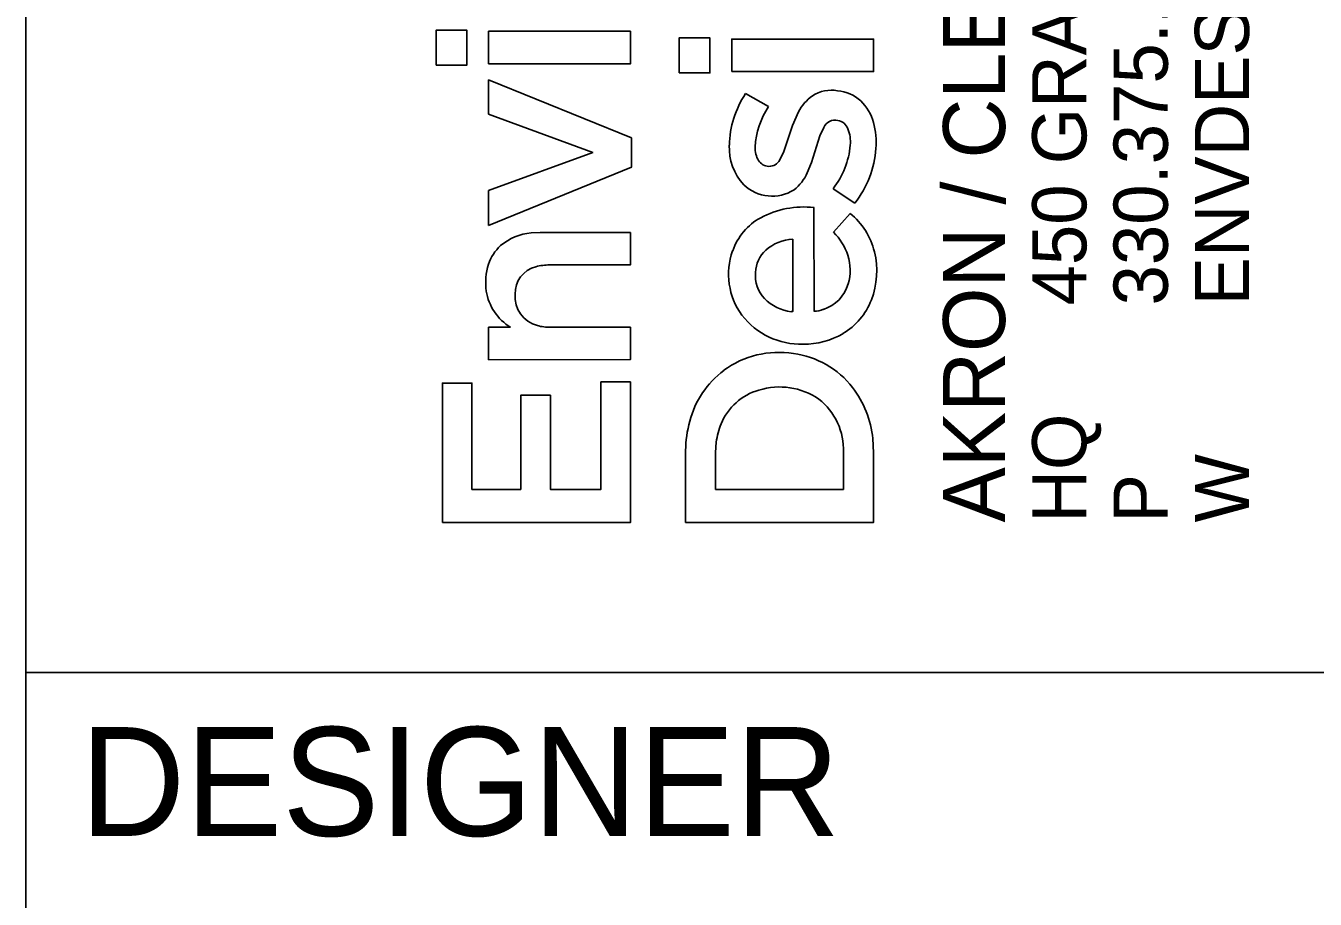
# Model space of a CAD drawing. Extents: x -0.3 to 34, y 0 to 22.
# Drawn here: x 32 to 33.185, y 2.292 to 3.094 of the extents above; entities that cross this region are included whole.
import ezdxf

# ---------------------------------------------------------------- set-up
doc = ezdxf.new("R2010")
doc.units = 0
doc.layers.add('RD_X_Misc_Items', color=7, linetype='Continuous')
doc.layers.add('SV_X_Control_Cells_Found', color=7, linetype='Continuous')

msp = doc.modelspace()

# ---------------------------------------------------------------- linework, layer by layer
at = {"layer": 'RD_X_Misc_Items'}
for p, q in [((32.3771, 3.0582), (32.3771, 3.0903)), ((32.3771, 3.0903), (32.4054, 3.0903)), ((32.4054, 3.0903), (32.4054, 3.0582)), ((32.4254, 3.0594), (32.4254, 3.0893)), ((32.4254, 3.0893), (32.5557, 3.0893)), ((32.5557, 3.0893), (32.5557, 3.0594)), ((32.6005, 3.0511), (32.6005, 3.0832)), ((32.6005, 3.0832), (32.6289, 3.0832)), ((32.6289, 3.0832), (32.6289, 3.0511)), ((32.6489, 3.0523), (32.6489, 3.0822)), ((32.6489, 3.0822), (32.7792, 3.0822)), ((32.7792, 3.0822), (32.7792, 3.0523)), ((32.4054, 3.0582), (32.3771, 3.0582)), ((32.5557, 3.0594), (32.4254, 3.0594)), ((32.6289, 3.0511), (32.6005, 3.0511)), ((32.7792, 3.0523), (32.6489, 3.0523)), ((32.4254, 3.0133), (32.4254, 3.0446)), ((32.4254, 3.0446), (32.5567, 2.9913)), ((32.6615, 3.0321), (32.6827, 3.0203)), ((32.5212, 2.978), (32.4254, 3.0133)), ((32.7048, 3.0026), (32.7104, 3.0153)), ((32.6967, 2.9787), (32.7048, 3.0026)), ((32.7334, 3.001), (32.7298, 2.9933)), ((32.5567, 2.9913), (32.5567, 2.9644)), ((32.7298, 2.9933), (32.7221, 2.9688)), ((32.4254, 2.9429), (32.5212, 2.978)), ((32.693, 2.9712), (32.6967, 2.9787)), ((32.5567, 2.9644), (32.4254, 2.9109)), ((32.7221, 2.9688), (32.7182, 2.9592)), ((32.4254, 2.9109), (32.4254, 2.9429)), ((32.7621, 2.9314), (32.742, 2.9447)), ((32.7245, 2.9275), (32.7246, 2.8319)), ((32.7423, 2.9046), (32.7577, 2.922)), ((32.4644, 2.904), (32.4729, 2.9044)), ((32.4729, 2.9044), (32.5557, 2.9044)), ((32.5557, 2.9044), (32.5557, 2.8746)), ((32.7049, 2.8318), (32.7049, 2.8983)), ((32.5557, 2.8746), (32.4814, 2.8746)), ((32.7036, 2.8317), (32.7049, 2.8318)), ((32.4254, 2.7875), (32.4254, 2.8173)), ((32.4254, 2.8173), (32.4455, 2.8173)), ((32.4822, 2.8173), (32.5557, 2.8173)), ((32.5557, 2.8173), (32.5557, 2.7876)), ((32.5557, 2.7876), (32.4254, 2.7875)), ((32.383, 2.6379), (32.383, 2.766)), ((32.383, 2.766), (32.4101, 2.766)), ((32.4101, 2.766), (32.4101, 2.6683)), ((32.5286, 2.6683), (32.5286, 2.7672)), ((32.5286, 2.7672), (32.5557, 2.7672)), ((32.5557, 2.7672), (32.5557, 2.6379)), ((32.455, 2.6683), (32.455, 2.7549)), ((32.455, 2.7549), (32.4822, 2.7549)), ((32.4822, 2.7549), (32.4822, 2.6683)), ((32.7785, 2.715), (32.7792, 2.7021)), ((32.6064, 2.638), (32.6064, 2.704)), ((32.6347, 2.7118), (32.6341, 2.7023)), ((32.6341, 2.7023), (32.6341, 2.6684)), ((32.7515, 2.6683), (32.7515, 2.7024)), ((32.7792, 2.7021), (32.7792, 2.638)), ((32.4101, 2.6683), (32.455, 2.6683)), ((32.4822, 2.6683), (32.5286, 2.6683)), ((32.6341, 2.6684), (32.7515, 2.6683)), ((32.5557, 2.6379), (32.383, 2.6379)), ((32.7792, 2.638), (32.6064, 2.638))]:
    msp.add_line(p, q, dxfattribs=at)
for points in [[(32.3771, 3.0582), (32.3771, 3.0903), (32.4054, 3.0903), (32.4054, 3.0582)], [(32.4254, 3.0594), (32.4254, 3.0893), (32.5557, 3.0893), (32.5557, 3.0594)], [(32.6005, 3.0511), (32.6005, 3.0832), (32.6289, 3.0832), (32.6289, 3.0511)], [(32.6489, 3.0523), (32.6489, 3.0822), (32.7792, 3.0822), (32.7792, 3.0523)], [(32.4254, 2.9109), (32.4254, 2.9429), (32.5212, 2.978), (32.4254, 3.0133), (32.4254, 3.0446), (32.5567, 2.9913), (32.5567, 2.9644)], [(32.383, 2.6379), (32.383, 2.766), (32.4101, 2.766), (32.4101, 2.6683), (32.455, 2.6683), (32.455, 2.7549), (32.4822, 2.7549), (32.4822, 2.6683), (32.5286, 2.6683), (32.5286, 2.7672), (32.5557, 2.7672), (32.5557, 2.6379)]]:
    msp.add_lwpolyline(points, close=True, dxfattribs=at)
for points in [[(32.6615, 3.0321), (32.6827, 3.0203)], [(32.693, 2.9712), (32.6967, 2.9787), (32.7048, 3.0026), (32.7104, 3.0153)], [(32.7334, 3.001), (32.7298, 2.9933), (32.7221, 2.9688), (32.7182, 2.9592)], [(32.7621, 2.9314), (32.742, 2.9447)], [(32.7245, 2.9275), (32.7246, 2.8319)], [(32.7423, 2.9046), (32.7577, 2.922)], [(32.4644, 2.904), (32.4729, 2.9044), (32.5557, 2.9044), (32.5557, 2.8746), (32.4814, 2.8746)], [(32.7036, 2.8317), (32.7049, 2.8318), (32.7049, 2.8983)], [(32.4254, 2.7875), (32.4254, 2.8173), (32.4455, 2.8173)], [(32.4822, 2.8173), (32.5557, 2.8173), (32.5557, 2.7876), (32.4254, 2.7875)], [(32.7785, 2.715), (32.7792, 2.7021), (32.7792, 2.638), (32.6064, 2.638)], [(32.6064, 2.638), (32.6064, 2.704)], [(32.6347, 2.7118), (32.6341, 2.7023), (32.6341, 2.6684), (32.7515, 2.6683), (32.7515, 2.7024)]]:
    msp.add_lwpolyline(points, dxfattribs=at)
for centre, radius, start, end in [((32.7406, 3.0026), 0.0326, 80.1719, 122.5197), ((32.7406, 3.0026), 0.0326, 80.1719, 122.5197), ((32.7428, 2.9982), 0.0367, 47.7934, 84.6892), ((32.7428, 2.9982), 0.0367, 47.7934, 84.6892), ((32.7364, 2.9826), 0.0897, 146.531, 178.7571), ((32.7364, 2.9826), 0.0897, 146.531, 178.7571), ((32.7466, 2.9971), 0.0405, 125.5118, 153.4159), ((32.7466, 2.9971), 0.0405, 125.5118, 153.4159), ((32.7379, 2.9946), 0.0427, 14.9966, 46.2063), ((32.7379, 2.9946), 0.0427, 14.9966, 46.2063), ((32.7452, 2.9789), 0.0749, 146.5112, 176.9101), ((32.7452, 2.9789), 0.0749, 146.5112, 176.9101), ((32.7438, 2.9963), 0.0114, 76.6609, 155.7053), ((32.7438, 2.9963), 0.0114, 76.6609, 155.7053), ((32.744, 2.9951), 0.0126, 21.5098, 78.5262), ((32.744, 2.9951), 0.0126, 21.5098, 78.5262), ((32.7259, 2.9877), 0.0321, 354.5726, 22.068), ((32.7259, 2.9877), 0.0321, 354.5726, 22.068), ((32.7104, 2.9867), 0.0712, 355.8306, 15.3914), ((32.7104, 2.9867), 0.0712, 355.8306, 15.3914), ((32.6967, 2.9824), 0.0501, 177.5366, 222.7932), ((32.6967, 2.9824), 0.0501, 177.5366, 222.7932), ((32.6931, 2.9823), 0.0228, 178.4747, 211.0868), ((32.6931, 2.9823), 0.0228, 178.4747, 211.0868), ((32.6825, 2.9915), 0.0757, 321.811, 354.7969), ((32.6825, 2.9915), 0.0757, 321.811, 354.7969), ((32.6895, 2.9882), 0.0922, 321.9777, 355.8738), ((32.6895, 2.9882), 0.0922, 321.9777, 355.8738), ((32.6833, 2.9767), 0.0115, 212.2368, 268.3777), ((32.6833, 2.9767), 0.0115, 212.2368, 268.3777), ((32.6834, 2.9759), 0.0107, 267.716, 333.7337), ((32.6834, 2.9759), 0.0107, 267.716, 333.7337), ((32.681, 2.9758), 0.0408, 308.0877, 335.9874), ((32.681, 2.9758), 0.0408, 308.0877, 335.9874), ((32.686, 2.9753), 0.0375, 225.9854, 302.4797), ((32.686, 2.9753), 0.0375, 225.9854, 302.4797), ((32.7152, 2.8441), 0.0838, 83.615, 118.2876), ((32.7152, 2.8441), 0.0838, 83.615, 118.2876), ((32.7024, 2.8691), 0.0558, 118.8308, 160.6244), ((32.7024, 2.8691), 0.0558, 118.8308, 160.6244), ((32.7174, 2.8717), 0.0644, 13.5336, 51.3615), ((32.7174, 2.8717), 0.0644, 13.5336, 51.3615), ((32.4687, 2.8543), 0.0499, 94.9696, 130.2225), ((32.4687, 2.8543), 0.0499, 94.9696, 130.2225), ((32.7038, 2.8656), 0.0549, 19.0357, 45.4406), ((32.7038, 2.8656), 0.0549, 19.0357, 45.4406), ((32.4635, 2.8626), 0.0402, 132.2219, 161.6818), ((32.4635, 2.8626), 0.0402, 132.2219, 161.6818), ((32.7079, 2.8561), 0.0424, 94.008, 130.8817), ((32.7079, 2.8561), 0.0424, 94.008, 130.8817), ((32.7104, 2.8661), 0.0644, 160.5201, 215.7831), ((32.7104, 2.8661), 0.0644, 160.5201, 215.7831), ((32.7005, 2.8663), 0.0298, 132.9851, 177.179), ((32.7005, 2.8663), 0.0298, 132.9851, 177.179), ((32.7107, 2.8697), 0.047, 344.6059, 17.007), ((32.7107, 2.8697), 0.047, 344.6059, 17.007), ((32.7064, 2.8692), 0.0758, 339.3542, 13.3785), ((32.7064, 2.8692), 0.0758, 339.3542, 13.3785), ((32.4787, 2.8582), 0.056, 162.2736, 187.7919), ((32.4787, 2.8582), 0.056, 162.2736, 187.7919), ((32.4748, 2.8487), 0.025, 103.6865, 182.2187), ((32.4748, 2.8487), 0.025, 103.6865, 182.2187), ((32.4811, 2.8286), 0.046, 89.6049, 105.3284), ((32.4811, 2.8286), 0.046, 89.6049, 105.3284), ((32.7017, 2.865), 0.0311, 175.0013, 223.283), ((32.7017, 2.865), 0.0311, 175.0013, 223.283), ((32.7224, 2.8671), 0.035, 288.0077, 343.5508), ((32.7224, 2.8671), 0.035, 288.0077, 343.5508), ((32.4703, 2.858), 0.0476, 188.962, 238.7037), ((32.4703, 2.858), 0.0476, 188.962, 238.7037), ((32.4773, 2.8456), 0.0276, 175.5854, 255.1439), ((32.4773, 2.8456), 0.0276, 175.5854, 255.1439), ((32.7089, 2.8736), 0.0423, 225.0619, 262.7974), ((32.7089, 2.8736), 0.0423, 225.0619, 262.7974), ((32.7247, 2.8522), 0.0202, 269.7003, 294.8711), ((32.7247, 2.8522), 0.0202, 269.7003, 294.8711), ((32.7189, 2.8652), 0.0626, 300.9427, 338.7323), ((32.7189, 2.8652), 0.0626, 300.9427, 338.7323), ((32.7125, 2.8705), 0.0687, 217.7452, 271.6543), ((32.7125, 2.8705), 0.0687, 217.7452, 271.6543), ((32.4818, 2.8595), 0.0422, 254.0916, 270.5284), ((32.4818, 2.8595), 0.0422, 254.0916, 270.5284), ((32.7155, 2.8724), 0.0706, 269.2048, 300.3341), ((32.7155, 2.8724), 0.0706, 269.2048, 300.3341), ((32.6923, 2.7079), 0.0864, 81.194, 125.9984), ((32.6923, 2.7079), 0.0864, 81.194, 125.9984), ((32.6946, 2.7113), 0.0827, 37.8521, 82.402), ((32.6946, 2.7113), 0.0827, 37.8521, 82.402), ((32.6939, 2.7089), 0.0865, 127.2362, 165.148), ((32.6939, 2.7089), 0.0865, 127.2362, 165.148), ((32.6928, 2.6986), 0.0639, 55.6727, 107.2093), ((32.6928, 2.6986), 0.0639, 55.6727, 107.2093), ((32.6859, 2.7057), 0.0931, 5.7333, 37.304), ((32.6859, 2.7057), 0.0931, 5.7333, 37.304), ((32.6889, 2.7078), 0.054, 106.1881, 157.3861), ((32.6889, 2.7078), 0.054, 106.1881, 157.3861), ((32.6929, 2.705), 0.0587, 357.4662, 52.2665), ((32.6929, 2.705), 0.0587, 357.4662, 52.2665), ((32.7143, 2.7028), 0.1078, 164.7861, 179.3704), ((32.7143, 2.7028), 0.1078, 164.7861, 179.3704), ((32.6983, 2.7039), 0.0641, 157.3571, 172.9275), ((32.6983, 2.7039), 0.0641, 157.3571, 172.9275)]:
    msp.add_arc(centre, radius, start, end, dxfattribs=at)
at = {"layer": 'SV_X_Control_Cells_Found'}
for p, q in [((32, 0.5), (32, 21.5)), ((32, 2.5), (33.5, 2.5))]:
    msp.add_line(p, q, dxfattribs=at)

# ---------------------------------------------------------------- texts
at = {"layer": 'RD_X_Misc_Items'}
for s, height, p in [('450 GRANT ST., AKRON, OH  44311', 0.049846, (32.9749, 2.8374)), ('AKRON / CLEVELAND / COLUMBUS', 0.056969, (32.9001, 2.638)), ('ENVDESIGNGROUP.COM', 0.049846, (33.1244, 2.8374)), ('330.375.1390', 0.049846, (33.0497, 2.8374)), ('HQ ', 0.04985, (32.9749, 2.638)), ('W', 0.0498, (33.1244, 2.638)), ('P', 0.0498, (33.0497, 2.638))]:
    msp.add_text(s, height=height, rotation=90, dxfattribs=at).set_placement(p)
msp.add_text('DESIGNER', height=0.1, dxfattribs=at).set_placement((32.05, 2.35))

doc.saveas('drawing.dxf')
